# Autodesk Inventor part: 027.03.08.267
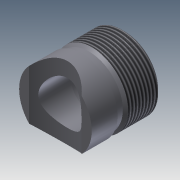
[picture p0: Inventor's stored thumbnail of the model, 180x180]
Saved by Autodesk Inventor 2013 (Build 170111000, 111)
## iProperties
Shininess: 25.0
Length Units: 11269
Angle Units: 11279
Time Units: 11290
Mass Units: 11283
Length Display Precision: 3
Angle Display Precision: 2
Created: 2001-08
Part Number: 027.03.08.267
Material: Steel, Mild
Document SubType Name: Modeling
Designer: SOleg
Density: 1 g/cm^3
Density: 0.0
Volumn: 0.0
Area: 0.0
PropertySet Name: Model Information
Control State: 0
Master: False
Checked Out: True
Checked Out Date: 2008-10-15
Last Check In Date: 2008-10-15
Author: SOleg
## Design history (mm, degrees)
sketch "Sketch1"
  geometry: L1 (151.133, 104.399)-(151.133, 119.399); L2 (151.133, 119.399)-(152.633, 119.399); L3 (152.633, 119.399)-(152.633, 123.899); L4 (152.633, 123.899)-(151.133, 125.399); L5 (151.133, 125.399)-(151.133, 144.399); L6 (151.133, 144.399)-(172.133, 144.399); L7 (172.133, 144.399)-(172.133, 104.399); L8 (172.133, 104.399)-(151.133, 104.399); L9 (172.133, 144.399)-(172.133, 104.399); 1 further point
  constraints: 18 end point, 1 other
  dimensions: "d1" = 40 distance of L6.end L7.end; "d3" = 21 distance of L5.end L6.end; "d5" = 21 distance of L7.end L1.start; "d7" = 25 vertical distance of L5.end L2.end; "d9" = 4.5 distance of L2.end L3.end; "d11" = 135 deg angle of L4 L3; "d13" = 19.5 horizontal distance of L3.end L6.end; "d31" = 172.13342 distance from line of point (0, 0) L7
revolve "RevolutionFull1" sketch "Sketch1" stored, may be unused: angle "d14" = 360 deg
chamfer "Chamfer1" distance "d15" = 1.6; stored, may be unused: second distance "d16" = 1.6, angle "d34" = 45 deg
sketch "Sketch2"
  geometry: C1 r 21 at (0, 0) reference
hole "Hole1" sketch "Sketch2" diameter "d18" = 25; stored, may be unused: countersink angle "d22" = 24 deg, drill point angle "d24" = 120 deg; dims "d19" = 6, "d20" = 33, "d21" = 2, "d23" = 8
sketch "Sketch3"
  geometry: L1 (193.133, 104.399)-(151.133, 104.399) reference; C1 r 20 at (172.133, 91.399)
  constraints: 1 centre point
  dimensions: "d26" = 40 diameter of C1; "d32" = 21 horizontal distance of C1.centre L1.end; "d33" = 7 distance edge to line of C1 L1
extrude "ExtrusionMidplane1" cut sketch "Sketch3" stored distance "d27" = 50; taper "d28" = 0 deg
thread "Thread1" dims "d29" = 10, "d30" = 0
body "Solid1"
other parameters: "d2" = 21 (derived), "d4" = 21 (derived), "d6" = 25 (derived), "d8" = 4.5 (derived), "d10" = 135 deg (derived), "d12" = 19.5 (derived), "d17" = 0
